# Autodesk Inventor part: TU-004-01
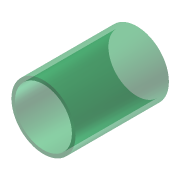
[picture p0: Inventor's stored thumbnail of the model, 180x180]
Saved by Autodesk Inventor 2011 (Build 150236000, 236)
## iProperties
Created: 2002-07
Part Number: TU-004-01
Material: Stainless Steel
Description: Cylinder Body- 35 mm
Document SubType Name: Modeling
Designer: PN
Mass: 184.955 g
Surface Area: 189.956 cm^2
Volume: 22.8904 cm^3
Density: 8.08 g/cm^3
Author: PN
Stroke_Length: 35.000 mm
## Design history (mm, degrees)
derived "Cylinder Body.ipt" dims "d0" = 46, "d1" = 40.85, "d2" = 67, "d3" = 0, "Stroke_Length" = 35
body "Solid1"
feature "Solid1::Cylinder Body.ipt" dims "d0" = 46, "d1" = 40.85, "d2" = 67, "d3" = 0, "Stroke_Length" = 35, "ScaleForDerivedMember" = 10
tag "TaggingFeature1"
